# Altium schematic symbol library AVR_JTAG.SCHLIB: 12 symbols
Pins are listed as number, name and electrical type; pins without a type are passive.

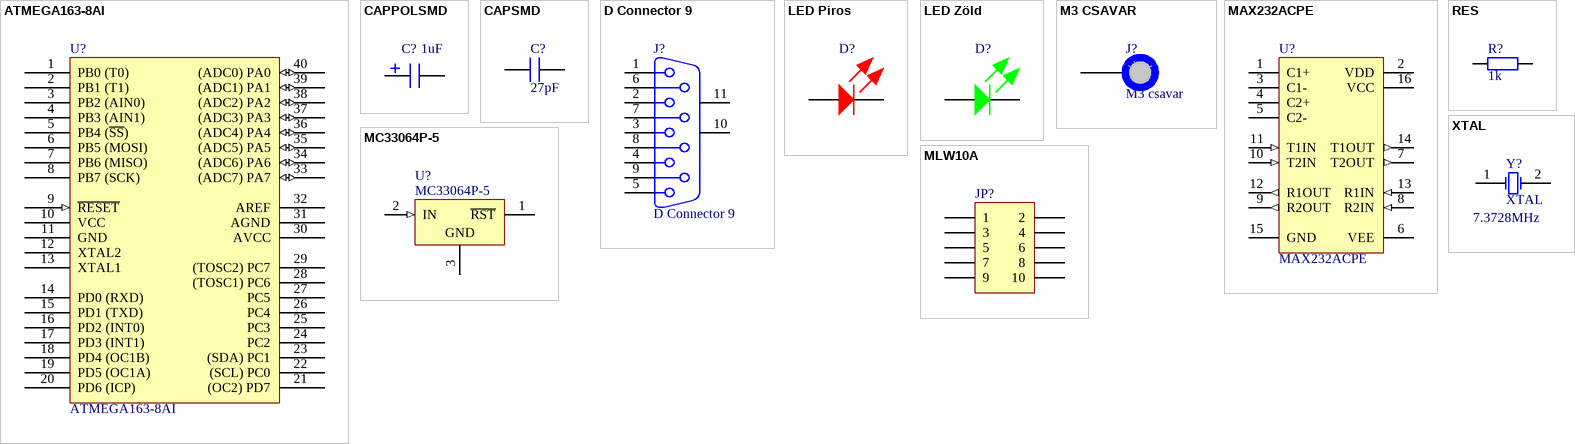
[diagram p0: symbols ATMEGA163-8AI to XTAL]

## ATMEGA163-8AI
designator U?
8 bit microcontroller; Manufacturer: Atmel; Class: 8-bit Microcontroller; Bolt: MSC
footprint DIP-40 (DIP40); pin to pad 9>20
pins: 1 PB0 (T0), 2 PB1 (T1), 3 PB2 (AIN0), 4 PB3 (AIN1), 5 PB4 (~{SS}), 6 PB5 (MOSI), 7 PB6 (MISO), 8 PB7 (SCK), 9 ~{RESET} (in), 10 VCC (power), 11 GND (power), 12 XTAL2, 13 XTAL1, 14 PD0 (RXD), 15 PD1 (TXD), 16 PD2 (INT0), 17 PD3 (INT1), 18 PD4 (OC1B), 19 PD5 (OC1A), 20 PD6 (ICP), 21 (OC2) PD7, 22 (SCL) PC0, 23 (SDA) PC1, 24 PC2, 25 PC3, 26 PC4, 27 PC5, 28 (TOSC1) PC6, 29 (TOSC2) PC7, 30 AVCC (power), 31 AGND (power), 32 AREF (power), 33 (ADC7) PA7 (io), 34 (ADC6) PA6 (io), 35 (ADC5) PA5 (io), 36 (ADC4) PA4 (io), 37 (ADC3) PA3 (io), 38 (ADC2) PA2 (io), 39 (ADC1) PA1 (io), 40 (ADC0) PA0 (io)

## CAPPOLSMD
designator C?  value 1uF
Capacitor Polarity SMD1206; Bolt: RET
footprint SMD1206 POL (Model Description)
signal-integrity model CAP POL3 (Capacitor)
simulation model CAP (Capacitor)
pins: 1, 2

## CAPSMD
designator C?  value 27pF
Capacitor SMD1206; Bolt: RET
footprint SMD1206 (Model Description)
signal-integrity model CAP (Capacitor)
simulation model CAP (Capacitor)
pins: 1, 2

## D Connector 9
designator J?
Receptacle Assembly, 9 Position, Right Angle; Manufacturer: Generic Components; Positions: 9
footprint DSUB9F90
signal-integrity model Connector
pins: 1, 2, 3, 4, 5, 6, 7, 8, 9, 10 MH1, 11 MH2

## LED Piros
designator D?
Piros Led 3mm; Bolt: RET
footprint LED 3MM; pin to pad 2>3
pins: 1, 2

## LED Zöld
designator D?
Zöld Led 3mm; Bolt: RET
footprint LED 3mm; pin to pad 2>3
pins: 1, 2

## M3 CSAVAR
designator J?, comment M3 csavar
M3 csavar hely
footprint M3 CSAVAR (M3 csavar furat)
pins: 1

## MAX232ACPE
designator U?
+5V Powered, Multi-Channel RS-232 Driver/Receiver; Manufacturer: Maxim; Class: Communication; SubClass: Transceiver; Bolt: RET
footprint DIP-16/X1.5
pins: 1 C1+, 2 VDD (power), 3 C1-, 4 C2+, 5 C2-, 6 VEE (power), 7 T2OUT (out), 8 R2IN (in), 9 R2OUT (out), 10 T2IN (in), 11 T1IN (in), 12 R1OUT (out), 13 R1IN (in), 14 T1OUT (out), 15 GND (power), 16 VCC (power)

## MC33064P-5
designator U?
Undervoltage Sensing Circuit; Manufacturer: ON Semiconductor; Class: Power Management; SubClass: Voltage Detector; Bolt: RET
footprint BCY-W3
pins: 1 ~{RST} (oc), 2 IN (in), 3 GND (power)

## MLW10A
designator JP?
Header, 5-Pin, Dual row, Right Angle; Manufacturer: Generic Components; Class: Connector; Bolt: RET
footprint MLW10A
signal-integrity model Connector
pins: 1, 2, 3, 4, 5, 6, 7, 8, 9, 10

## RES
designator R?  value 1k
Resistor SMD1206, 1% fémréteg; Bolt: RET
footprint SMD1206 (Model Description)
signal-integrity model RES (Resistor)
simulation model RES (Resistor)
pins: 1, 2

## XTAL
designator Y?  value 7.3728MHz
Crystal Oscillator; Manufacturer: Generic Components; Bolt: RET
footprint XTAL
simulation model XTAL (Spice Subcircuit)
pins: 1 OSC1, 2 OSC2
